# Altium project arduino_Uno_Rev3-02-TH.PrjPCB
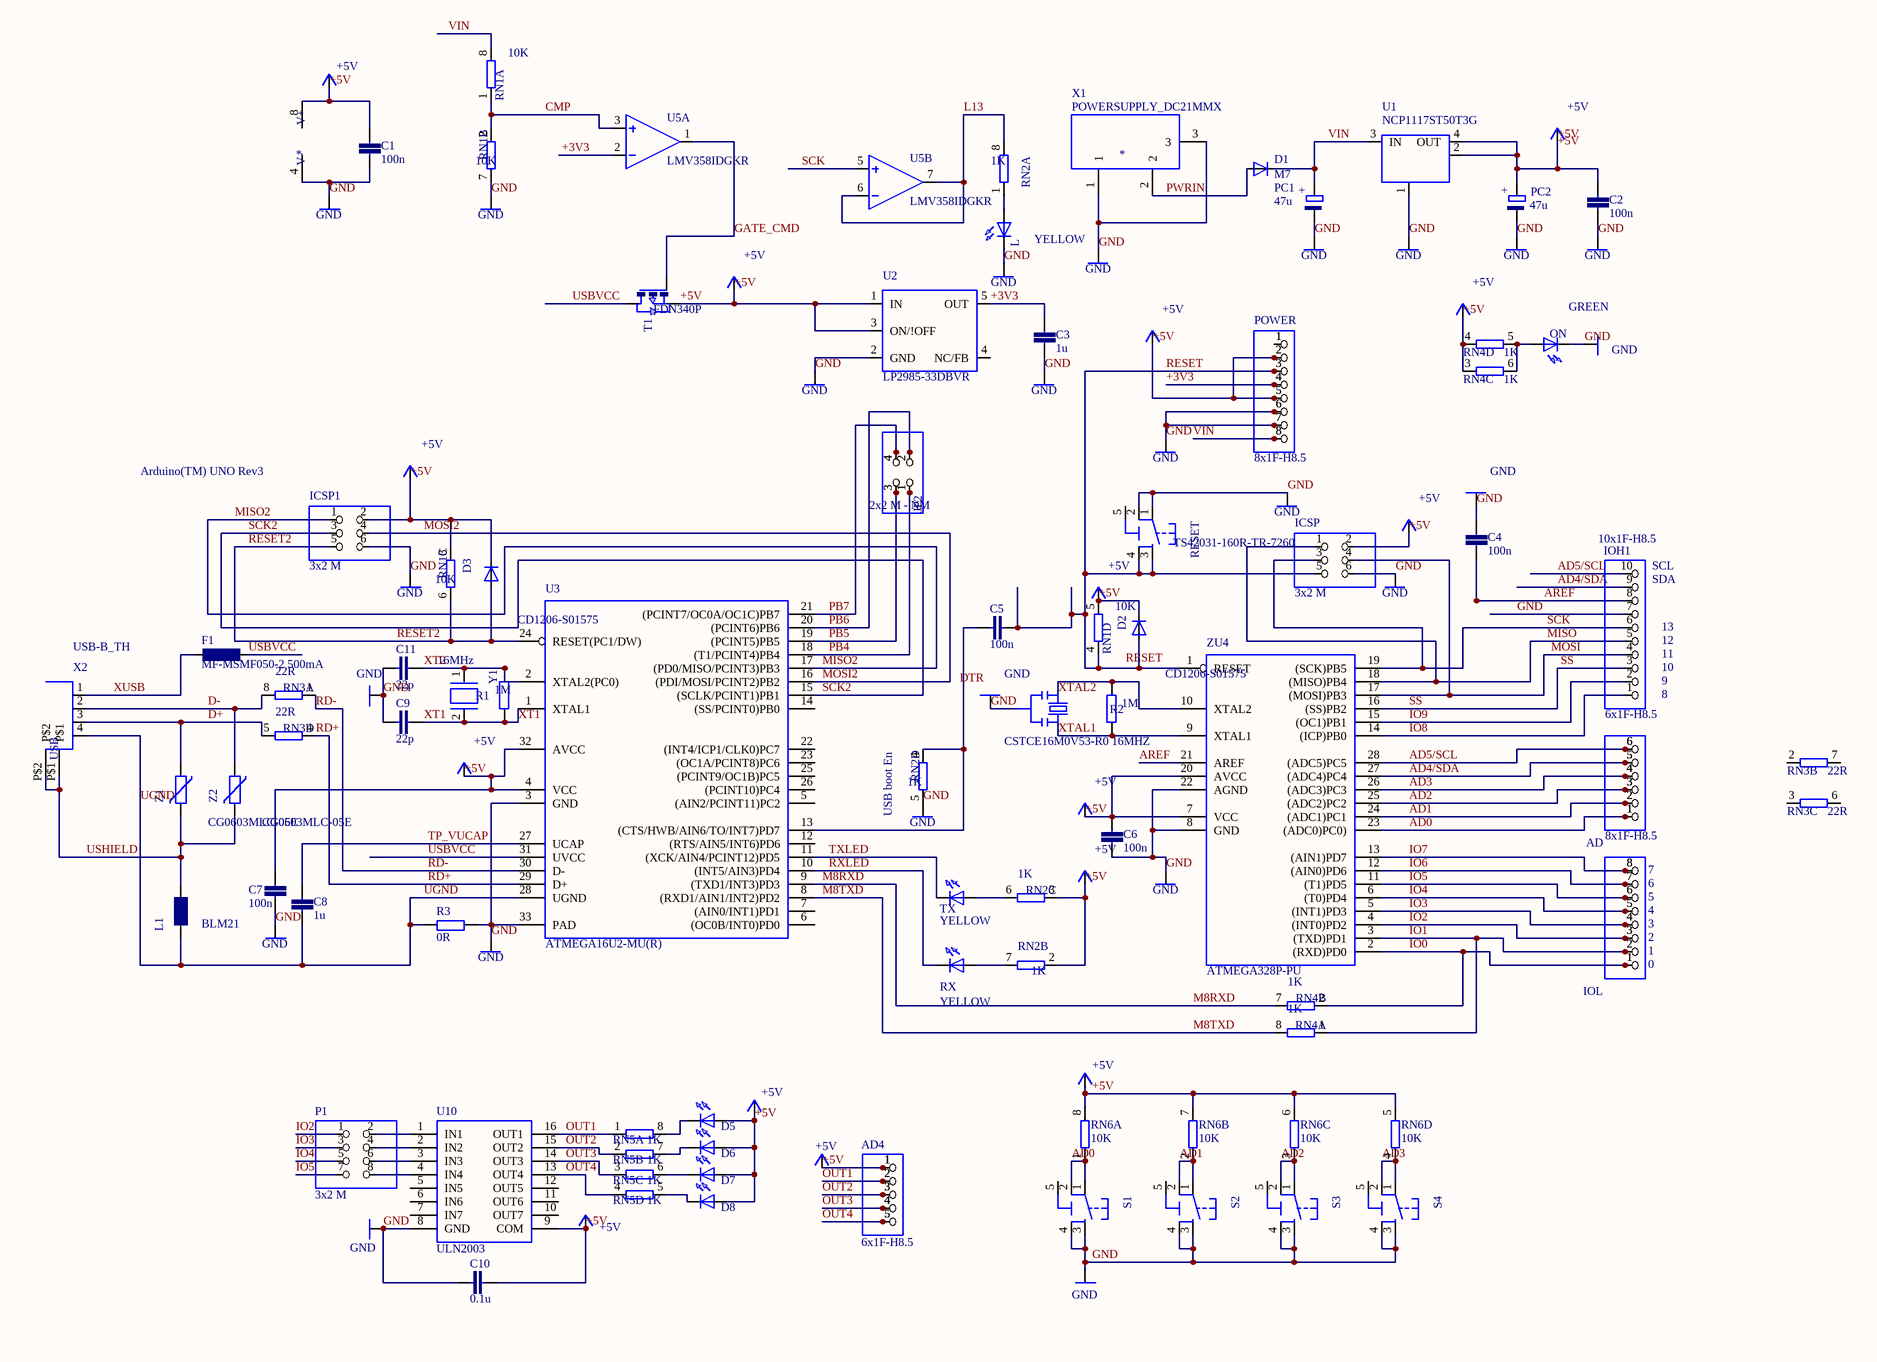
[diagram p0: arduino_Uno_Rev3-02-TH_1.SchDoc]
1 sheet, 101 parts. Net scope: global (net labels, ports and power ports of the same name join across sheets).
Board file: arduino_Uno_Rev3-02-TH2.PcbDoc

## Sheet arduino_Uno_Rev3-02-TH_1.SchDoc
size 351 x 252 mm; SheetNumber: 0; SheetTotal: 0

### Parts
AD  6x1F-H8.5  [1X06]
AD4  6x1F-H8.5  [1X05]
C1  100n  [R0603-ROUND]
C2  100n  [R0603-ROUND]
C3  1u  [R0603-ROUND]
C4  100n  [R0603-ROUND]
C5  100n  [R0603-ROUND]
C6  100n  [R0603-ROUND]
C7  100n  [R0603-ROUND]
C8  1u  [R0603-ROUND]
C9  22p  [R0603-ROUND]
C10  0.1u  [R0603-ROUND]
C11  22p  [R0603-ROUND]
D1  M7  [SMB]
D2  CD1206-S01575  [MINIMELF]
D3  CD1206-S01575  [MINIMELF]
D5  YELLOW  [CHIP-LED0805]  (value not drawn)
D6  YELLOW  [CHIP-LED0805]  (value not drawn)
D7  YELLOW  [CHIP-LED0805]  (value not drawn)
D8  YELLOW  [CHIP-LED0805]  (value not drawn)
F1  MF-MSMF050-2 500mA  [L1812]
GND1  GND
GND2  GND
GND3  GND
GND4  GND
GND5  GND
GND7  GND
GND8  GND
GND9  GND
GND10  GND
GND11  GND
GND12  GND
GND13  GND
GND14  GND
GND15  GND
GND16  GND
GND17  GND
GND18  GND
GND19  GND
GND20  GND
GND21  GND
GND22  GND
GND23  GND
GND24  GND
GND25  GND
ICSP  3x2 M  [2X03]
ICSP1  3x2 M  [2X03]
IOH1  10x1F-H8.5  [1X10@1]
IOL  8x1F-H8.5  [1X08]
JP2  2x2 M - NM  [2X02]
L  YELLOW  [CHIP-LED0805]
L1  BLM21  [0805]
ON  GREEN  [CHIP-LED0805]
P1  3x2 M  [2X04]
P+1  +5V
P+2  +5V
P+3  +5V
P+4  +5V
P+5  +5V
P+6  +5V
P+7  +5V
P+8  +5V
P+9  +5V
P+10  +5V
P+11  +5V
P+12  +5V
P+13  +5V
P+14  +5V
P+15  +5V
PC1  47u  [PANASONIC_D]
PC2  47u  [PANASONIC_D]
POWER  8x1F-H8.5  [1X08]
R1  1M  [R0603-ROUND]
R2  1M  [R0603-ROUND]
R3  0R  [R0603-ROUND]
RESET  TS42031-160R-TR-7260  [TS42]
RN1  10K  [CAY16]  (parts A,B,C,D of 4)
RN2  1K  [CAY16]  (parts A,B,C,D of 4)
RN3  22R  [CAY16]  (parts A,B,C,D of 4)
RN4  1K  [CAY16]  (parts A,B,C,D of 4)
RN5  1K  [CAY16]  (parts A,B,C,D of 4)
RN6  10K  [CAY16]  (parts A,B,C,D of 4)
RX  YELLOW  [CHIP-LED0805]
S1  TS42031-160R-TR-7260  [TS42]  (value not drawn)
S2  TS42031-160R-TR-7260  [TS42]  (value not drawn)
S3  TS42031-160R-TR-7260  [TS42]  (value not drawn)
S4  TS42031-160R-TR-7260  [TS42]  (value not drawn)
T1  FDN340P  [SOT-23]
TX  YELLOW  [CHIP-LED0805]
U1  NCP1117ST50T3G  [SOT223]
U2  LP2985-33DBVR  [SOT23-DBV]
U3  ATMEGA16U2-MU(R)  [MLF32]
U5  LMV358IDGKR  [MSOP08]  (parts A,B,C of 3)
U10  ULN2003  [sop16]
X1  *  [POWERSUPPLY_DC-21MM]
X2  USB-B_TH  [PN61729]
Y1  16MHz  [QS]
Y2  CSTCE16M0V53-R0 16MHZ  [RESONATOR]
Z1  CG0603MLC-05E  [CT/CN0603]
Z2  CG0603MLC-05E  [CT/CN0603]
ZU4  ATMEGA328P-PU  [DIL28-3]

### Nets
+3V3: C3.1 POWER.4 U2.5(OUT) U5.2(-IN)
+5V: AD4.1 C1.1 C2.1 C6.2 C7.1 C10.2 D2.C D3.C D5.A D6.A D7.A D8.A ICSP.2 ICSP1.2 P+1.0(+5V) P+2.0(+5V) P+3.0(+5V) P+4.0(+5V) P+5.0(+5V) P+6.0(+5V) P+7.0(+5V) P+8.0(+5V) P+9.0(+5V) P+10.0(+5V) P+11.0(+5V) P+12.0(+5V) P+13.0(+5V) P+14.0(+5V) P+15.0(+5V) PC2.+ POWER.2 POWER.5 RN1.3 RN1.5 RN2.2 RN2.3 RN4.3 RN4.4 RN6.5 RN6.6 RN6.7 RN6.8 T1.2(S) U1.2(OUT@1) U1.4(OUT) U2.1(IN) U2.3(ON/!OFF) U3.4(VCC) U3.32(AVCC) U5.8(V+) U10.9(COM) ZU4.7(VCC) ZU4.20(AVCC)
AD0: AD.1 RN6.1 S1.1 S1.2 ZU4.23((ADC0)PC0))
AD1: AD.2 RN6.2 S2.1 S2.2 ZU4.24((ADC1)PC1)
AD2: AD.3 RN6.3 S3.1 S3.2 ZU4.25((ADC2)PC2)
AD3: AD.4 RN6.4 S4.1 S4.2 ZU4.26((ADC3)PC3)
AD4/SDA: AD.5 IOH1.9 ZU4.27((ADC4)PC4)
AD5/SCL: AD.6 IOH1.10 ZU4.28((ADC5)PC5)
AREF: C4.1 IOH1.8 ZU4.21(AREF)
CMP: RN1.1 RN1.2 U5.3(+IN)
D+: RN3.5 X2.3 Z1.1
D-: RN3.8 X2.2 Z2.1
GATE_CMD: T1.3(G) U5.1(OUT)
GND: C1.2 C2.2 C3.2 C4.2 C6.1 C7.2 C9.1 C10.1 C11.1 GND1.0(GND) GND2.0(GND) GND3.0(GND) GND4.0(GND) GND5.0(GND) GND7.0(GND) GND8.0(GND) GND9.0(GND) GND10.0(GND) GND11.0(GND) GND12.0(GND) GND13.0(GND) GND14.0(GND) GND15.0(GND) GND16.0(GND) GND17.0(GND) GND18.0(GND) GND19.0(GND) GND20.0(GND) GND21.0(GND) GND22.0(GND) GND23.0(GND) GND24.0(GND) GND25.0(GND) ICSP.6 ICSP1.6 IOH1.7 L.C ON.C PC1.- PC2.- POWER.6 POWER.7 R3.1 RESET.1 RESET.2 RN1.7 RN2.5 S1.3 S1.4 S2.3 S2.4 S3.3 S3.4 S4.3 S4.4 U1.1(GND/ADJ) U2.2(GND) U3.3(GND) U3.33(PAD) U5.4(V-) U10.8(GND) X1.1 X1.3 Y2.2 ZU4.8(GND) ZU4.22(AGND)
IO0: IOL.1 RN4.2 ZU4.2((RXD)PD0)
IO1: IOL.2 RN4.1 ZU4.3((TXD)PD1)
IO2: IOL.3 P1.1 ZU4.4((INT0)PD2)
IO3: IOL.4 P1.3 ZU4.5((INT1)PD3)
IO4: IOL.5 P1.5 ZU4.6((T0)PD4)
IO5: IOL.6 P1.7 ZU4.11((T1)PD5)
IO6: IOL.7 ZU4.12((AIN0)PD6)
IO7: IOL.8 ZU4.13((AIN1)PD7)
IO8: IOH1.1 ZU4.14((ICP)PB0)
IO9: IOH1.2 ZU4.15((OC1)PB1)
L13: RN2.8 U5.6(-IN) U5.7(OUT)
M8RXD: RN4.7 U3.9((TXD1/INT3)PD3)
M8TXD: RN4.8 U3.8((RXD1/AIN1/INT2)PD2)
MISO: ICSP.1 IOH1.5 ZU4.18((MISO)PB4)
MISO2: ICSP1.1 U3.17((PD0/MISO/PCINT3)PB3)
MOSI: ICSP.4 IOH1.4 ZU4.17((MOSI)PB3)
MOSI2: ICSP1.4 U3.16((PDI/MOSI/PCINT2)PB2)
OUT1: AD4.2 RN5.1 U10.16(OUT1)
OUT2: AD4.3 RN5.2 U10.15(OUT2)
OUT3: AD4.4 RN5.3 U10.14(OUT3)
OUT4: AD4.5 RN5.4 U10.13(OUT4)
PB4: JP2.1 U3.18((T1/PCINT4)PB4)
PB5: JP2.3 U3.19((PCINT5)PB5)
PB6: JP2.2 U3.20((PCINT6)PB6)
PB7: JP2.4 U3.21((PCINT7/OC0A/OC1C)PB7)
PWRIN: D1.A X1.2
RD+: RN3.4 U3.29(D+)
RD-: RN3.1 U3.30(D-)
RESET: C5.2 D2.A ICSP.5 POWER.3 RESET.3 RESET.4 RN1.4 ZU4.1(RESET)
RESET2: D3.A ICSP1.5 RN1.6 U3.24(RESET(PC1/DW))
RXLED: RX.C U3.10((INT5/AIN3)PD4)
SCK: ICSP.3 IOH1.6 U5.5(+IN) ZU4.19((SCK)PB5)
SCK2: ICSP1.3 U3.15((SCLK/PCINT1)PB1)
SS: IOH1.3 ZU4.16((SS)PB2)
TP_VUCAP: C8.1 U3.27(UCAP)
TXLED: TX.C U3.11((XCK/AIN4/PCINT12)PD5)
UGND: C8.2 L1.1 R3.2 U3.28(UGND) X2.4
USBVCC: F1.1 T1.1(D) U3.31(UVCC)
USHIELD: L1.2 X2.P$1 X2.P$2 Z1.2 Z2.2
VIN: D1.C PC1.+ POWER.8 RN1.8 U1.3(IN)
XT1: C9.2 R1.1 U3.1(XTAL1) Y1.2
XT2: C11.2 R1.2 U3.2(XTAL2(PC0)) Y1.1
XTAL1: R2.1 Y2.3 ZU4.9(XTAL1)
XTAL2: R2.2 Y2.1 ZU4.10(XTAL2)
XUSB: F1.2 X2.1
NetC5_1: C5.1 RN2.4 U3.13((CTS/HWB/AIN6/TO/INT7)PD7)
NetD5_C: D5.C RN5.8
NetD6_C: D6.C RN5.7
NetD7_C: D7.C RN5.6
NetD8_C: D8.C RN5.5
NetL_A: L.A RN2.1
NetON_A: ON.A RN4.5 RN4.6
NetP1_2: P1.2 U10.1(IN1)
NetP1_4: P1.4 U10.2(IN2)
NetP1_6: P1.6 U10.3(IN3)
NetP1_8: P1.8 U10.4(IN4)
NetRN2_6: RN2.6 TX.A
NetRN2_7: RN2.7 RX.A

Not connected (* = marked no-connect by the designer): POWER 1; RESET 5(5-GND); RN3 2(1) 3(1) 6(2) 7(2); S1 5(5-GND); S2 5(5-GND); S3 5(5-GND); S4 5(5-GND); U2 4(NC/FB); U3 5((AIN2/PCINT11)PC2) 6((OC0B/INT0)PD0) 7((AIN0/INT1)PD1) 12((RTS/AIN5/INT6)PD6) 14((SS/PCINT0)PB0) 22((INT4/ICP1/CLK0)PC7) 23((OC1A/PCINT8)PC6) 25((PCINT9/OC1B)PC5) 26((PCINT10)PC4); U10 5(IN5) 6(IN6) 7(IN7) 10(OUT7) 11(OUT6) 12(OUT5)

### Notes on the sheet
- Arduino(TM) UNO Rev3
- (near IOH1) SCL
- (near IOH1) SDA
- (near IOH1) 13
- (near IOH1) 8
- (near IOH1) 9
- (near IOH1) 10
- (near IOH1) 11
- (near IOH1) 12
- USB boot En
- (near IOL) 5
- (near IOL) 6
- (near IOL) 7
- (near IOL) 0
- (near IOL) 1
- (near IOL) 2
- (near IOL) 3
- (near IOL) 4
- Labels drawn without touching a wire or pin: DTR, RESET

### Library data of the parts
AD = PINHD-1X6
AD4 = PINHD-1X5
C1-C11 = C-EU0603-RND
D1 = DIODE-SMB
D2 D3 = DIODE-MINIMELF
D5-D8 L ON RX TX = LEDCHIP-LED0805
F1 = L-EUL1812
ICSP ICSP1 = PINHD-2X3
IOH1 = PINHD-1X10_ARD
IOL POWER = PINHD-1X8
JP2 = PINHD-2X2
L1 = WE-CBF_0805
P1 = PINHD-2X4
PC1 PC2 = CPOL-EUD
R1-R3 = R-EU_R0603
RESET S1-S4 = TS42
RN1-RN6 = 4R-NCAY16
T1 = PMOSSOT23
U1 = MC33269ST-3.3T3
U2 = LP2985-XXDBVR33
U3 = ATMEGA16U2-MU
U5 = LMV358MMX
X1 = POWERSUPPLY_DC21MMX
X2 = PN61729
Y1 = XTAL/S
Y2 = RESONATORMU
Z1 Z2 = VARISTORCN0603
